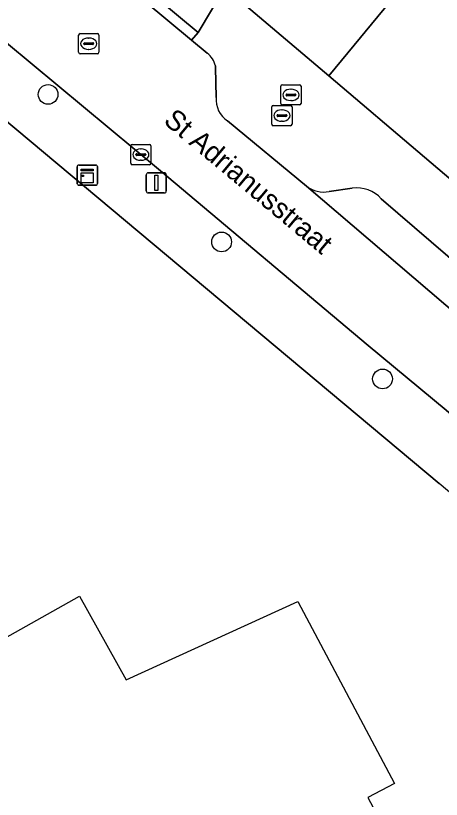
# Model space of a CAD drawing. Extents: x 162073 to 163043, y 381818 to 382561.
# Drawn here: x 162553.66 to 162574.72, y 382030.78 to 382069.57 of the extents above; entities that cross this region are included whole.
import ezdxf

# ---------------------------------------------------------------- set-up
doc = ezdxf.new("R2010")
doc.units = 0
for name, color, linetype in [('IMGEO_Boom', 7, 'Continuous'), ('IMGEO_Brandkraan', 7, 'Continuous'), ('IMGEO_Erf', 7, 'Continuous'), ('IMGEO_Kast', 7, 'Continuous'), ('IMGEO_Kolk', 7, 'Continuous'), ('IMGEO_Lichtmast', 7, 'Continuous'), ('IMGEO_Openbare_ruimte_label', 7, 'Continuous'), ('IMGEO_Pand_vergunning_verleend', 7, 'Continuous'), ('IMGEO_Parkeervlak_open', 7, 'Continuous'), ('IMGEO_Rijbaan_lokaal_open', 7, 'Continuous'), ('IMGEO_Rioolput', 7, 'Continuous'), ('IMGEO_Voetpad_open', 7, 'Continuous')]:
    doc.layers.add(name, color=color, linetype=linetype)

msp = doc.modelspace()

# ---------------------------------------------------------------- linework, layer by layer
at = {"layer": 'IMGEO_Boom'}
for centre in [(162555.268, 382065.67), (162563.851, 382058.369), (162571.812, 382051.59)]:
    msp.add_circle(centre, 0.489, dxfattribs=at)
at = {"layer": 'IMGEO_Brandkraan'}
for p, q in [((162566.781, 382065.222), (162566.781, 382066.074)), ((162566.856, 382066.148), (162567.708, 382066.148)), ((162567.269, 382065.928), (162567.294, 382065.928)), ((162567.782, 382066.074), (162567.782, 382065.222)), ((162567.04, 382065.642), (162567.04, 382065.654)), ((162567.478, 382065.605), (162567.08, 382065.605)), ((162567.083, 382065.691), (162567.481, 382065.691)), ((162567.524, 382065.654), (162567.524, 382065.642)), ((162567.708, 382065.148), (162566.856, 382065.148)), ((162567.292, 382065.368), (162567.267, 382065.368))]:
    msp.add_line(p, q, dxfattribs=at)
for points in [[(162566.781, 382065.222), (162566.781, 382066.074)], [(162566.856, 382066.148), (162567.708, 382066.148)], [(162567.782, 382066.074), (162567.782, 382065.222)], [(162567.708, 382065.148), (162566.856, 382065.148)]]:
    msp.add_lwpolyline(points, dxfattribs=at)
for centre, radius, start, end in [((162566.858, 382066.072), 0.0765, 91.552, 178.448), ((162566.858, 382066.072), 0.0765, 91.552, 178.448), ((162567.706, 382066.072), 0.0765, 1.552, 88.448), ((162567.706, 382066.072), 0.0765, 1.552, 88.448), ((162567.08, 382065.651), 0.0403, 85.8775, 175.7526), ((162567.077, 382065.641), 0.0366, 178.938, 274.7102), ((162567.481, 382065.648), 0.043, 264.8664, 352.4533), ((162567.485, 382065.653), 0.0386, 1.7309, 96.639), ((162566.858, 382065.224), 0.0765, 181.552, 268.448), ((162566.858, 382065.224), 0.0765, 181.552, 268.448), ((162567.706, 382065.224), 0.0765, 271.552, 358.448), ((162567.706, 382065.224), 0.0765, 271.552, 358.448)]:
    msp.add_arc(centre, radius, start, end, dxfattribs=at)
for centre, major_axis, ratio, start_param, end_param in [((162567.268, 382065.648), (-0.387, 0.002), 0.722429, 4.712389, 7.853982), ((162567.293, 382065.648), (-0.39, 0.002), 0.717154, 1.570796, 4.712389)]:
    msp.add_ellipse(centre, major_axis=major_axis, ratio=ratio, start_param=start_param, end_param=end_param, dxfattribs=at)
at = {"layer": 'IMGEO_Erf'}
for points in [[(162610.06, 382116.173), (162569.158, 382066.59), (162583.359, 382054.51), (162585.935, 382052.319), (162587.039, 382053.571), (162630.776, 382000)], [(162574.615, 382046.411), (162523.276, 382089.432), (162521.435, 382087.22), (162500, 382061.465), (162495.527, 382056.09), (162485.32, 382043.802), (162496.476, 382022.946), (162500, 382016.409), (162500.583, 382015.328), (162500.694, 382015.122), (162500, 382014.237), (162498.228, 382011.978), (162496.617, 382012.958), (162485.8, 382000), (162479.39, 381992.322), (162463.245, 381972.97)]]:
    msp.add_lwpolyline(points, dxfattribs=at)
msp.add_arc((162494.336, 381948.449), 126.654, 42.88512, 50.66569, dxfattribs=at)
at = {"layer": 'IMGEO_Kast'}
for p, q in [((162556.707, 382061.252), (162556.707, 382062.093)), ((162556.707, 382062.093), (162556.707, 382061.252)), ((162556.782, 382062.177), (162557.623, 382062.177)), ((162557.623, 382062.177), (162556.782, 382062.177)), ((162557.707, 382062.102), (162557.707, 382061.261)), ((162557.707, 382061.261), (162557.707, 382062.102)), ((162557.632, 382061.177), (162556.791, 382061.177)), ((162556.791, 382061.177), (162557.632, 382061.177))]:
    msp.add_line(p, q, dxfattribs=at)
for points in [[(162556.902, 382061.967), (162557.502, 382061.967), (162557.502, 382061.882), (162556.902, 382061.882), (162556.902, 382061.967)], [(162556.902, 382061.792), (162557.502, 382061.792), (162557.502, 382061.303), (162556.902, 382061.303), (162556.902, 382061.792)]]:
    msp.add_lwpolyline(points, dxfattribs=at)
msp.add_circle((162556.986, 382061.641), 0.0377, dxfattribs=at)
for centre, start, end in [((162556.785, 382062.099), 92.4484, 184.2845), ((162556.785, 382062.099), 92.4484, 184.2845), ((162557.629, 382062.099), 2.4484, 94.2845), ((162557.629, 382062.099), 2.4484, 94.2845), ((162556.785, 382061.255), 182.4484, 274.2845), ((162556.785, 382061.255), 182.4484, 274.2845), ((162557.629, 382061.255), 272.4484, 4.2845), ((162557.629, 382061.255), 272.4484, 4.2845)]:
    msp.add_arc(centre, 0.0779, start, end, dxfattribs=at)
at = {"layer": 'IMGEO_Kolk'}
for p, q in [((162566.409, 382065.124), (162567.261, 382065.124)), ((162566.334, 382064.198), (162566.334, 382065.05)), ((162566.822, 382064.904), (162566.847, 382064.904)), ((162567.335, 382065.05), (162567.335, 382064.198)), ((162566.593, 382064.618), (162566.593, 382064.63)), ((162567.031, 382064.581), (162566.633, 382064.581)), ((162566.636, 382064.667), (162567.034, 382064.667)), ((162566.845, 382064.344), (162566.82, 382064.344)), ((162567.077, 382064.63), (162567.077, 382064.618)), ((162567.261, 382064.124), (162566.409, 382064.124)), ((162559.43, 382063.193), (162560.282, 382063.193)), ((162559.355, 382062.267), (162559.355, 382063.119)), ((162559.843, 382062.973), (162559.868, 382062.973)), ((162560.356, 382063.119), (162560.356, 382062.267)), ((162559.614, 382062.687), (162559.614, 382062.699)), ((162560.052, 382062.65), (162559.654, 382062.65)), ((162559.657, 382062.736), (162560.055, 382062.736)), ((162559.866, 382062.413), (162559.841, 382062.413)), ((162560.098, 382062.699), (162560.098, 382062.687)), ((162560.282, 382062.193), (162559.43, 382062.193))]:
    msp.add_line(p, q, dxfattribs=at)
for points in [[(162566.409, 382065.124), (162567.261, 382065.124)], [(162566.334, 382064.198), (162566.334, 382065.05)], [(162567.335, 382065.05), (162567.335, 382064.198)], [(162567.261, 382064.124), (162566.409, 382064.124)], [(162559.43, 382063.193), (162560.282, 382063.193)], [(162559.355, 382062.267), (162559.355, 382063.119)], [(162560.356, 382063.119), (162560.356, 382062.267)], [(162560.282, 382062.193), (162559.43, 382062.193)]]:
    msp.add_lwpolyline(points, dxfattribs=at)
for centre, radius, start, end in [((162566.411, 382065.048), 0.0765, 91.552, 178.448), ((162566.411, 382065.048), 0.0765, 91.552, 178.448), ((162567.259, 382065.048), 0.0765, 1.552, 88.448), ((162567.259, 382065.048), 0.0765, 1.552, 88.448), ((162566.633, 382064.627), 0.0403, 85.8775, 175.7526), ((162566.63, 382064.617), 0.0366, 178.938, 274.7102), ((162567.034, 382064.624), 0.043, 264.8664, 352.4533), ((162567.038, 382064.629), 0.0386, 1.7309, 96.639), ((162566.411, 382064.2), 0.0765, 181.552, 268.448), ((162566.411, 382064.2), 0.0765, 181.552, 268.448), ((162567.259, 382064.2), 0.0765, 271.552, 358.448), ((162567.259, 382064.2), 0.0765, 271.552, 358.448), ((162559.432, 382063.117), 0.0765, 91.552, 178.448), ((162559.432, 382063.117), 0.0765, 91.552, 178.448), ((162560.28, 382063.117), 0.0765, 1.552, 88.448), ((162560.28, 382063.117), 0.0765, 1.552, 88.448), ((162559.654, 382062.696), 0.0403, 85.8775, 175.7526), ((162559.651, 382062.686), 0.0366, 178.938, 274.7102), ((162560.055, 382062.693), 0.043, 264.8664, 352.4533), ((162560.059, 382062.698), 0.0386, 1.7309, 96.639), ((162559.432, 382062.269), 0.0765, 181.552, 268.448), ((162559.432, 382062.269), 0.0765, 181.552, 268.448), ((162560.28, 382062.269), 0.0765, 271.552, 358.448), ((162560.28, 382062.269), 0.0765, 271.552, 358.448)]:
    msp.add_arc(centre, radius, start, end, dxfattribs=at)
for centre, major_axis, ratio, start_param, end_param in [((162566.821, 382064.624), (-0.387, 0.002), 0.722429, 4.712389, 7.853982), ((162566.846, 382064.624), (-0.39, 0.002), 0.717154, 1.570796, 4.712389), ((162559.842, 382062.693), (-0.387, 0.002), 0.722429, 4.712389, 7.853982), ((162559.867, 382062.693), (-0.39, 0.002), 0.717154, 1.570796, 4.712389)]:
    msp.add_ellipse(centre, major_axis=major_axis, ratio=ratio, start_param=start_param, end_param=end_param, dxfattribs=at)
at = {"layer": 'IMGEO_Lichtmast'}
for p, q in [((162560.123, 382060.892), (162560.123, 382061.692)), ((162560.123, 382061.692), (162560.123, 382060.892)), ((162560.223, 382061.792), (162561.013, 382061.792)), ((162561.013, 382061.792), (162560.223, 382061.792)), ((162561.113, 382061.692), (162561.113, 382060.892)), ((162561.113, 382060.892), (162561.113, 382061.692)), ((162561.013, 382060.792), (162560.223, 382060.792)), ((162560.223, 382060.792), (162561.013, 382060.792))]:
    msp.add_line(p, q, dxfattribs=at)
msp.add_lwpolyline([(162560.543, 382061.667), (162560.693, 382061.667), (162560.693, 382060.917), (162560.543, 382060.917), (162560.543, 382061.667)], dxfattribs=at)
for centre, start, end in [((162560.223, 382061.692), 90, 180), ((162560.223, 382061.692), 90, 180), ((162561.013, 382061.692), 0, 90), ((162561.013, 382061.692), 360, 90), ((162560.223, 382060.892), 180, 270), ((162560.223, 382060.892), 180, 270), ((162561.013, 382060.892), 270, 0), ((162561.013, 382060.892), 270, 0)]:
    msp.add_arc(centre, 0.1, start, end, dxfattribs=at)
at = {"layer": 'IMGEO_Pand_vergunning_verleend'}
msp.add_lwpolyline([(162506.081, 382012.787), (162537.921, 382030.563), (162540.97, 382025.099), (162552.035, 382031.277), (162550.142, 382034.668), (162552.563, 382036.019), (162551.527, 382037.874), (162556.827, 382040.832), (162559.133, 382036.702), (162567.615, 382040.58), (162572.407, 382031.568), (162571.087, 382030.866), (162573.731, 382025.895), (162561.053, 382019.153), (162561.748, 382017.847), (162515.96, 381993.499)], close=True, dxfattribs=at)
at = {"layer": 'IMGEO_Parkeervlak_open'}
for points in [[(162568.044, 382061.134), (162579.468, 382051.383), (162580.692, 382052.802), (162571.751, 382060.51)], [(162570.315, 382061.024), (162569.175, 382060.862)]]:
    msp.add_lwpolyline(points, dxfattribs=at)
for centre, radius, start, end in [((162568.918, 382062.282), 1.443, 232.7156, 280.2393), ((162570.543, 382059.399), 1.641, 42.6153, 97.9962)]:
    msp.add_arc(centre, radius, start, end, dxfattribs=at)
at = {"layer": 'IMGEO_Rijbaan_lokaal_open'}
for points in [[(162563.139, 382067.712), (162562.365, 382068.359), (162558.855, 382071.293), (162556.529, 382073.226), (162548.068, 382080.256), (162539.638, 382087.264), (162538.14, 382088.51), (162536.674, 382089.721), (162529.956, 382095.27)], [(162526.502, 382090.663), (162528.495, 382088.989), (162536.729, 382082.148), (162544.264, 382075.847), (162553.211, 382068.229), (162560.822, 382061.89), (162571.093, 382053.249), (162574.964, 382050.041), (162580.499, 382045.158), (162584.603, 382041.27)], [(162563.578, 382065.52), (162563.549, 382067.004), (162563.547, 382067.086)], [(162583.153, 382048.232), (162584.378, 382049.625), (162584.003, 382049.948), (162581.447, 382052.151), (162580.692, 382052.802), (162579.468, 382051.383), (162568.044, 382061.134), (162564.146, 382064.364)]]:
    msp.add_lwpolyline(points, dxfattribs=at)
for centre, radius, start, end in [((162562.385, 382066.774), 1.203, 15.0051, 51.184), ((162564.831, 382065.418), 1.257, 175.3416, 236.9928)]:
    msp.add_arc(centre, radius, start, end, dxfattribs=at)
at = {"layer": 'IMGEO_Rioolput'}
for p, q in [((162556.777, 382067.756), (162556.777, 382068.608)), ((162556.852, 382068.682), (162557.704, 382068.682)), ((162557.778, 382068.608), (162557.778, 382067.756)), ((162557.036, 382068.176), (162557.036, 382068.188)), ((162557.079, 382068.225), (162557.477, 382068.225)), ((162557.265, 382068.462), (162557.29, 382068.462)), ((162557.52, 382068.188), (162557.52, 382068.176)), ((162557.474, 382068.139), (162557.076, 382068.139)), ((162557.288, 382067.902), (162557.263, 382067.902)), ((162557.704, 382067.682), (162556.852, 382067.682))]:
    msp.add_line(p, q, dxfattribs=at)
for points in [[(162556.777, 382067.756), (162556.777, 382068.608)], [(162556.852, 382068.682), (162557.704, 382068.682)], [(162557.778, 382068.608), (162557.778, 382067.756)], [(162557.704, 382067.682), (162556.852, 382067.682)]]:
    msp.add_lwpolyline(points, dxfattribs=at)
for centre, radius, start, end in [((162556.854, 382068.606), 0.0765, 91.552, 178.448), ((162556.854, 382068.606), 0.0765, 91.552, 178.448), ((162557.702, 382068.606), 0.0765, 1.552, 88.448), ((162557.702, 382068.606), 0.0765, 1.552, 88.448), ((162557.076, 382068.185), 0.0403, 85.8775, 175.7526), ((162557.481, 382068.187), 0.0386, 1.7309, 96.639), ((162557.073, 382068.175), 0.0366, 178.938, 274.7102), ((162557.477, 382068.182), 0.043, 264.8664, 352.4533), ((162556.854, 382067.758), 0.0765, 181.552, 268.448), ((162556.854, 382067.758), 0.0765, 181.552, 268.448), ((162557.702, 382067.758), 0.0765, 271.552, 358.448), ((162557.702, 382067.758), 0.0765, 271.552, 358.448)]:
    msp.add_arc(centre, radius, start, end, dxfattribs=at)
for centre, major_axis, ratio, start_param, end_param in [((162557.264, 382068.182), (-0.387, 0.002), 0.722429, 4.712389, 7.853982), ((162557.289, 382068.182), (-0.39, 0.002), 0.717154, 1.570796, 4.712389)]:
    msp.add_ellipse(centre, major_axis=major_axis, ratio=ratio, start_param=start_param, end_param=end_param, dxfattribs=at)
at = {"layer": 'IMGEO_Voetpad_open'}
for points in [[(162610.06, 382116.173), (162603.635, 382119.248), (162603.172, 382118.715), (162602.191, 382117.527), (162602.523, 382117.255), (162605.577, 382114.723), (162593.727, 382100.46), (162592.91, 382099.538), (162581.728, 382085.956), (162581.041, 382085.025), (162569.225, 382070.759), (162566.191, 382073.321), (162565.762, 382073.683), (162565.272, 382073.089), (162564.01, 382070.969), (162569.158, 382066.59)], [(162562.746, 382075.204), (162560.737, 382076.887), (162558.462, 382074.97), (162556.848, 382073.61), (162559.766, 382071.177), (162562.684, 382068.743), (162564.01, 382070.969), (162565.272, 382073.089)], [(162556.529, 382073.226), (162558.855, 382071.293), (162562.365, 382068.359), (162562.684, 382068.743), (162559.766, 382071.177), (162556.848, 382073.61)]]:
    msp.add_lwpolyline(points, close=True, dxfattribs=at)
for points in [[(162584.603, 382041.27), (162580.499, 382045.158), (162574.964, 382050.041), (162571.093, 382053.249), (162560.822, 382061.89), (162553.211, 382068.229), (162544.264, 382075.847), (162536.729, 382082.148), (162528.495, 382088.989), (162526.502, 382090.663)], [(162518.359, 382089.726), (162521.435, 382087.22), (162523.276, 382089.432), (162574.615, 382046.411)], [(162569.158, 382066.59), (162564.01, 382070.969), (162562.684, 382068.743), (162562.365, 382068.359), (162563.139, 382067.712)], [(162563.547, 382067.086), (162563.549, 382067.004), (162563.578, 382065.52)], [(162571.751, 382060.51), (162580.692, 382052.802), (162581.447, 382052.151), (162583.359, 382054.51), (162569.158, 382066.59)], [(162564.146, 382064.364), (162568.044, 382061.134)], [(162569.175, 382060.862), (162570.315, 382061.024)]]:
    msp.add_lwpolyline(points, dxfattribs=at)
for centre, radius, start, end in [((162562.385, 382066.774), 1.203, 15.0051, 51.184), ((162564.831, 382065.418), 1.257, 175.3416, 236.9928), ((162568.918, 382062.282), 1.443, 232.7156, 280.2393), ((162570.543, 382059.399), 1.641, 42.6153, 97.9962), ((162494.336, 381948.449), 126.654, 42.88512, 50.66569)]:
    msp.add_arc(centre, radius, start, end, dxfattribs=at)

# ---------------------------------------------------------------- texts
at = {"layer": 'IMGEO_Openbare_ruimte_label'}
msp.add_text('St Adrianusstraat', height=1, rotation=320.1944, dxfattribs=at).set_placement((162560.927, 382064.279))

doc.saveas('drawing.dxf')
